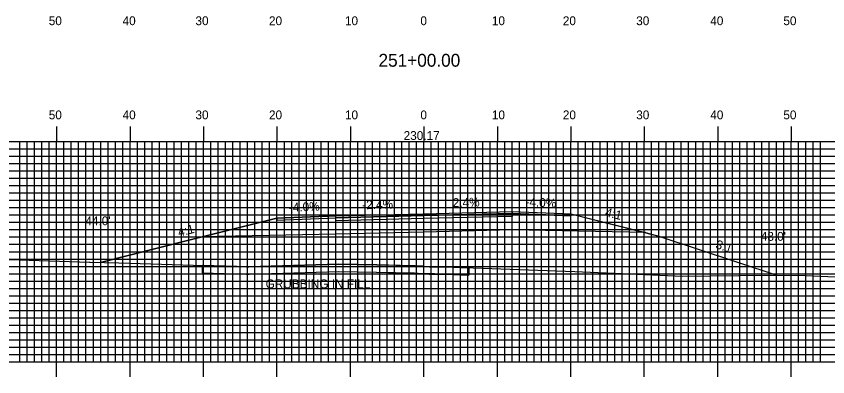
# Model space of a CAD drawing. Extents: x 1803897 to 1804240, y 442591 to 442811.
# Drawn here: x 1804007.2 to 1804117.6, y 442696.7 to 442745.7 of the extents above; entities that cross this region are included whole.
import ezdxf

# ---------------------------------------------------------------- set-up
doc = ezdxf.new("R2010")
doc.units = 0
for name, color, linetype in [('ANNOTATION', 7, 'Continuous'), ('D_Roadway_Centerline', 7, 'Continuous'), ('D_Roadway_Centerline_Text', 7, 'Continuous'), ('D_Roadway_Edge_Shoulder', 7, 'Continuous'), ('D_Roadway_Edge_TW', 7, 'Continuous'), ('D_Roadway_Pavement', 7, 'Continuous'), ('D_Roadway_SlopeLines', 7, 'Continuous'), ('D_Roadway_SubGrade', 7, 'Continuous'), ('D_Text_Standard', 7, 'Continuous'), ('GRUBBING IN FILL', 7, 'Continuous'), ('H_V ANNOTATION', 7, 'Continuous'), ('MAJOR', 7, 'Continuous'), ('MINOR', 7, 'Continuous'), ('S_Roadway_Centerline', 7, 'Continuous')]:
    doc.layers.add(name, color=color, linetype=linetype)

msp = doc.modelspace()

# ---------------------------------------------------------------- linework, layer by layer
at = {"layer": 'D_Roadway_Centerline'}
msp.add_lwpolyline([(1804018.63, 442712.22), (1804030.65, 442715.22), (1804032.48, 442715.68), (1804042.65, 442718.22), (1804050.65, 442718.54), (1804062.65, 442718.83), (1804074.65, 442719.12), (1804082.65, 442718.8), (1804092.83, 442716.26), (1804094.65, 442715.8), (1804110.67, 442710.46)], dxfattribs=at)
at = {"layer": 'D_Roadway_Edge_Shoulder'}
for points in [[(1804074.65, 442719.12), (1804082.65, 442718.8), (1804082.65, 442718.55), (1804074.65, 442718.87)], [(1804050.65, 442718.54), (1804042.65, 442718.22), (1804042.65, 442717.97), (1804050.65, 442718.29)]]:
    msp.add_lwpolyline(points, close=True, dxfattribs=at)
at = {"layer": 'D_Roadway_Edge_TW'}
msp.add_lwpolyline([(1804050.65, 442718.29), (1804050.65, 442718.54), (1804062.65, 442718.83), (1804074.65, 442719.12), (1804074.65, 442718.87), (1804062.65, 442718.58)], close=True, dxfattribs=at)
at = {"layer": 'D_Roadway_Pavement'}
msp.add_lwpolyline([(1804050.65, 442717.88), (1804050.65, 442718.29), (1804062.65, 442718.58), (1804074.65, 442718.87), (1804074.65, 442718.45), (1804062.65, 442718.16)], close=True, dxfattribs=at)
at = {"layer": 'D_Roadway_SlopeLines'}
for points in [[(1804042.65, 442718.22), (1804032.48, 442715.68), (1804030.65, 442715.22), (1804018.63, 442712.22)], [(1804082.65, 442718.8), (1804094.65, 442715.8), (1804110.67, 442710.46)]]:
    msp.add_lwpolyline(points, dxfattribs=at)
at = {"layer": 'D_Roadway_SubGrade'}
msp.add_lwpolyline([(1804050.65, 442716.04), (1804032.48, 442715.68), (1804042.65, 442718.22), (1804042.65, 442717.97), (1804050.65, 442718.29), (1804062.65, 442718.58), (1804074.65, 442718.87), (1804082.65, 442718.55), (1804082.65, 442718.8), (1804092.83, 442716.26), (1804074.65, 442716.62), (1804062.65, 442716.33)], close=True, dxfattribs=at)
at = {"layer": 'GRUBBING IN FILL'}
for p, q in [((1804032.48, 442711.79), (1804032.48, 442710.79)), ((1804032.48, 442711.79), (1804032.48, 442710.79)), ((1804068.75, 442711.48), (1804068.75, 442710.48)), ((1804068.75, 442711.48), (1804068.75, 442710.48)), ((1804065.57, 442710.59), (1804068.75, 442710.48)), ((1804065.57, 442710.59), (1804068.75, 442710.48))]:
    msp.add_line(p, q, dxfattribs=at)
for points in [[(1804032.48, 442711.79), (1804032.48, 442710.79), (1804035.47, 442710.7), (1804038.86, 442710.61), (1804044.94, 442710.79), (1804051.01, 442710.97), (1804056.2, 442710.87), (1804062.65, 442710.68), (1804062.65, 442711.68), (1804056.22, 442711.87), (1804051, 442711.97), (1804044.91, 442711.79), (1804038.82, 442711.61)], [(1804032.48, 442711.79), (1804032.48, 442710.79), (1804035.47, 442710.7), (1804038.86, 442710.61), (1804044.94, 442710.79), (1804051.01, 442710.97), (1804056.2, 442710.87), (1804062.65, 442710.68), (1804062.65, 442711.68), (1804056.22, 442711.87), (1804051, 442711.97), (1804044.91, 442711.79), (1804038.82, 442711.61)], [(1804062.65, 442711.68), (1804065.59, 442711.59), (1804068.75, 442711.48), (1804068.75, 442710.48), (1804065.57, 442710.59), (1804062.65, 442710.68)], [(1804062.65, 442711.68), (1804065.59, 442711.59), (1804068.75, 442711.48), (1804068.75, 442710.48), (1804065.57, 442710.59), (1804062.65, 442710.68)]]:
    msp.add_lwpolyline(points, close=True, dxfattribs=at)
msp.add_lwpolyline([(1804032.48, 442710.79), (1804038.45, 442710.61), (1804038.66, 442710.6), (1804038.86, 442710.61), (1804051.01, 442710.97), (1804061.39, 442710.77), (1804063.35, 442710.63), (1804065.57, 442710.59), (1804065.57, 442710.59)], dxfattribs=at)
msp.add_lwpolyline([(1804032.48, 442710.79), (1804038.45, 442710.61), (1804038.66, 442710.6), (1804038.86, 442710.61), (1804051.01, 442710.97), (1804061.39, 442710.77), (1804063.35, 442710.63), (1804065.57, 442710.59), (1804065.57, 442710.59)], dxfattribs=at)
at = {"layer": 'MAJOR'}
for p, q in [((1804012.65, 442730.67), (1804012.65, 442728.67)), ((1804022.65, 442730.67), (1804022.65, 442728.67)), ((1804032.65, 442730.67), (1804032.65, 442728.67)), ((1804042.65, 442730.67), (1804042.65, 442728.67)), ((1804052.65, 442730.67), (1804052.65, 442728.67)), ((1804062.65, 442730.67), (1804062.65, 442728.67)), ((1804072.65, 442730.67), (1804072.65, 442728.67)), ((1804082.65, 442730.67), (1804082.65, 442728.67)), ((1804092.65, 442730.67), (1804092.65, 442728.67)), ((1804102.65, 442730.67), (1804102.65, 442728.67)), ((1804112.65, 442730.67), (1804112.65, 442728.67)), ((1803922.65, 442728.67), (1804202.65, 442728.67)), ((1803922.65, 442728.67), (1804202.65, 442728.67)), ((1804012.65, 442698.67), (1804012.65, 442728.67)), ((1804022.65, 442698.67), (1804022.65, 442728.67)), ((1804032.65, 442698.67), (1804032.65, 442728.67)), ((1804042.65, 442698.67), (1804042.65, 442728.67)), ((1804052.65, 442698.67), (1804052.65, 442728.67)), ((1804062.65, 442698.67), (1804062.65, 442728.67)), ((1804072.65, 442698.67), (1804072.65, 442728.67)), ((1804082.65, 442698.67), (1804082.65, 442728.67)), ((1804092.65, 442698.67), (1804092.65, 442728.67)), ((1804102.65, 442698.67), (1804102.65, 442728.67)), ((1804112.65, 442698.67), (1804112.65, 442728.67)), ((1803922.65, 442723.67), (1804202.65, 442723.67)), ((1803922.65, 442718.67), (1804202.65, 442718.67)), ((1803922.65, 442713.67), (1804202.65, 442713.67)), ((1803922.65, 442708.67), (1804202.65, 442708.67)), ((1803922.65, 442703.67), (1804202.65, 442703.67)), ((1803922.65, 442698.67), (1804202.65, 442698.67)), ((1803922.65, 442698.67), (1804202.65, 442698.67)), ((1804012.65, 442696.66), (1804012.65, 442698.67)), ((1804022.65, 442696.66), (1804022.65, 442698.67)), ((1804032.65, 442696.66), (1804032.65, 442698.67)), ((1804042.65, 442696.66), (1804042.65, 442698.67)), ((1804052.65, 442696.66), (1804052.65, 442698.67)), ((1804062.65, 442696.66), (1804062.65, 442698.67)), ((1804072.65, 442696.66), (1804072.65, 442698.67)), ((1804082.65, 442696.66), (1804082.65, 442698.67)), ((1804092.65, 442696.66), (1804092.65, 442698.67)), ((1804102.65, 442696.66), (1804102.65, 442698.67)), ((1804112.65, 442696.66), (1804112.65, 442698.67))]:
    msp.add_line(p, q, dxfattribs=at)
at = {"layer": 'MINOR'}
for p, q in [((1803922.65, 442727.67), (1804202.65, 442727.67)), ((1804007.65, 442698.67), (1804007.65, 442728.67)), ((1804008.65, 442698.67), (1804008.65, 442728.67)), ((1804009.65, 442698.67), (1804009.65, 442728.67)), ((1804010.65, 442698.67), (1804010.65, 442728.67)), ((1804011.65, 442698.67), (1804011.65, 442728.67)), ((1804013.65, 442698.67), (1804013.65, 442728.67)), ((1804014.65, 442698.67), (1804014.65, 442728.67)), ((1804015.65, 442698.67), (1804015.65, 442728.67)), ((1804016.65, 442698.67), (1804016.65, 442728.67)), ((1804017.65, 442698.67), (1804017.65, 442728.67)), ((1804018.65, 442698.67), (1804018.65, 442728.67)), ((1804019.65, 442698.67), (1804019.65, 442728.67)), ((1804020.65, 442698.67), (1804020.65, 442728.67)), ((1804021.65, 442698.67), (1804021.65, 442728.67)), ((1804023.65, 442698.67), (1804023.65, 442728.67)), ((1804024.65, 442698.67), (1804024.65, 442728.67)), ((1804025.65, 442698.67), (1804025.65, 442728.67)), ((1804026.65, 442698.67), (1804026.65, 442728.67)), ((1804027.65, 442698.67), (1804027.65, 442728.67)), ((1804028.65, 442698.67), (1804028.65, 442728.67)), ((1804029.65, 442698.67), (1804029.65, 442728.67)), ((1804030.65, 442698.67), (1804030.65, 442728.67)), ((1804031.65, 442698.67), (1804031.65, 442728.67)), ((1804033.65, 442698.67), (1804033.65, 442728.67)), ((1804034.65, 442698.67), (1804034.65, 442728.67)), ((1804035.65, 442698.67), (1804035.65, 442728.67)), ((1804036.65, 442698.67), (1804036.65, 442728.67)), ((1804037.65, 442698.67), (1804037.65, 442728.67)), ((1804038.65, 442698.67), (1804038.65, 442728.67)), ((1804039.65, 442698.67), (1804039.65, 442728.67)), ((1804040.65, 442698.67), (1804040.65, 442728.67)), ((1804041.65, 442698.67), (1804041.65, 442728.67)), ((1804043.65, 442698.67), (1804043.65, 442728.67)), ((1804044.65, 442698.67), (1804044.65, 442728.67)), ((1804045.65, 442698.67), (1804045.65, 442728.67)), ((1804046.65, 442698.67), (1804046.65, 442728.67)), ((1804047.65, 442698.67), (1804047.65, 442728.67)), ((1804048.65, 442698.67), (1804048.65, 442728.67)), ((1804049.65, 442698.67), (1804049.65, 442728.67)), ((1804050.65, 442698.67), (1804050.65, 442728.67)), ((1804051.65, 442698.67), (1804051.65, 442728.67)), ((1804053.65, 442698.67), (1804053.65, 442728.67)), ((1804054.65, 442698.67), (1804054.65, 442728.67)), ((1804055.65, 442698.67), (1804055.65, 442728.67)), ((1804056.65, 442698.67), (1804056.65, 442728.67)), ((1804057.65, 442698.67), (1804057.65, 442728.67)), ((1804058.65, 442698.67), (1804058.65, 442728.67)), ((1804059.65, 442698.67), (1804059.65, 442728.67)), ((1804060.65, 442698.67), (1804060.65, 442728.67)), ((1804061.65, 442698.67), (1804061.65, 442728.67)), ((1804063.65, 442698.67), (1804063.65, 442728.67)), ((1804064.65, 442698.67), (1804064.65, 442728.67)), ((1804065.65, 442698.67), (1804065.65, 442728.67)), ((1804066.65, 442698.67), (1804066.65, 442728.67)), ((1804067.65, 442698.67), (1804067.65, 442728.67)), ((1804068.65, 442698.67), (1804068.65, 442728.67)), ((1804069.65, 442698.67), (1804069.65, 442728.67)), ((1804070.65, 442698.67), (1804070.65, 442728.67)), ((1804071.65, 442698.67), (1804071.65, 442728.67)), ((1804073.65, 442698.67), (1804073.65, 442728.67)), ((1804074.65, 442698.67), (1804074.65, 442728.67)), ((1804075.65, 442698.67), (1804075.65, 442728.67)), ((1804076.65, 442698.67), (1804076.65, 442728.67)), ((1804077.65, 442698.67), (1804077.65, 442728.67)), ((1804078.65, 442698.67), (1804078.65, 442728.67)), ((1804079.65, 442698.67), (1804079.65, 442728.67)), ((1804080.65, 442698.67), (1804080.65, 442728.67)), ((1804081.65, 442698.67), (1804081.65, 442728.67)), ((1804083.65, 442698.67), (1804083.65, 442728.67)), ((1804084.65, 442698.67), (1804084.65, 442728.67)), ((1804085.65, 442698.67), (1804085.65, 442728.67)), ((1804086.65, 442698.67), (1804086.65, 442728.67)), ((1804087.65, 442698.67), (1804087.65, 442728.67)), ((1804088.65, 442698.67), (1804088.65, 442728.67)), ((1804089.65, 442698.67), (1804089.65, 442728.67)), ((1804090.65, 442698.67), (1804090.65, 442728.67)), ((1804091.65, 442698.67), (1804091.65, 442728.67)), ((1804093.65, 442698.67), (1804093.65, 442728.67)), ((1804094.65, 442698.67), (1804094.65, 442728.67)), ((1804095.65, 442698.67), (1804095.65, 442728.67)), ((1804096.65, 442698.67), (1804096.65, 442728.67)), ((1804097.65, 442698.67), (1804097.65, 442728.67)), ((1804098.65, 442698.67), (1804098.65, 442728.67)), ((1804099.65, 442698.67), (1804099.65, 442728.67)), ((1804100.65, 442698.67), (1804100.65, 442728.67)), ((1804101.65, 442698.67), (1804101.65, 442728.67)), ((1804103.65, 442698.67), (1804103.65, 442728.67)), ((1804104.65, 442698.67), (1804104.65, 442728.67)), ((1804105.65, 442698.67), (1804105.65, 442728.67)), ((1804106.65, 442698.67), (1804106.65, 442728.67)), ((1804107.65, 442698.67), (1804107.65, 442728.67)), ((1804108.65, 442698.67), (1804108.65, 442728.67)), ((1804109.65, 442698.67), (1804109.65, 442728.67)), ((1804110.65, 442698.67), (1804110.65, 442728.67)), ((1804111.65, 442698.67), (1804111.65, 442728.67)), ((1804113.65, 442698.67), (1804113.65, 442728.67)), ((1804114.65, 442698.67), (1804114.65, 442728.67)), ((1804115.65, 442698.67), (1804115.65, 442728.67)), ((1804116.65, 442698.67), (1804116.65, 442728.67)), ((1803922.65, 442726.67), (1804202.65, 442726.67)), ((1803922.65, 442725.67), (1804202.65, 442725.67)), ((1803922.65, 442724.67), (1804202.65, 442724.67)), ((1803922.65, 442722.67), (1804202.65, 442722.67)), ((1803922.65, 442721.67), (1804202.65, 442721.67)), ((1803922.65, 442720.67), (1804202.65, 442720.67)), ((1803922.65, 442719.67), (1804202.65, 442719.67)), ((1803922.65, 442717.67), (1804202.65, 442717.67)), ((1803922.65, 442716.67), (1804202.65, 442716.67)), ((1803922.65, 442715.67), (1804202.65, 442715.67)), ((1803922.65, 442714.67), (1804202.65, 442714.67)), ((1803922.65, 442712.67), (1804202.65, 442712.67)), ((1803922.65, 442711.67), (1804202.65, 442711.67)), ((1803922.65, 442710.67), (1804202.65, 442710.67)), ((1803922.65, 442709.67), (1804202.65, 442709.67)), ((1803922.65, 442707.67), (1804202.65, 442707.67)), ((1803922.65, 442706.67), (1804202.65, 442706.67)), ((1803922.65, 442705.67), (1804202.65, 442705.67)), ((1803922.65, 442704.67), (1804202.65, 442704.67)), ((1803922.65, 442702.67), (1804202.65, 442702.67)), ((1803922.65, 442701.67), (1804202.65, 442701.67)), ((1803922.65, 442700.67), (1804202.65, 442700.67)), ((1803922.65, 442699.67), (1804202.65, 442699.67))]:
    msp.add_line(p, q, dxfattribs=at)
at = {"layer": 'S_Roadway_Centerline'}
msp.add_lwpolyline([(1804004.8, 442712.66), (1804017.13, 442712.26), (1804017.17, 442712.26), (1804017.21, 442712.26), (1804021.12, 442712.14), (1804038.49, 442711.61), (1804038.64, 442711.6), (1804038.82, 442711.61), (1804051, 442711.97), (1804061.44, 442711.77), (1804063.39, 442711.63), (1804065.59, 442711.59), (1804083.2, 442710.98), (1804090.63, 442710.67), (1804097.91, 442710.33), (1804105.51, 442710.43), (1804110.2, 442710.46), (1804114.65, 442710.42), (1804127.57, 442709.85)], dxfattribs=at)

# ---------------------------------------------------------------- texts
at = {"layer": 'ANNOTATION'}
for s, rotation, p in [('-4.0%', 2.2906, (1804044.29, 442719.09)), ('-2.4%', 1.3748, (1804054.27, 442719.43)), ('2.4%', 1.3748, (1804066.59, 442719.73)), ('-4.0%', 357.7094, (1804076.45, 442719.85)), ('4:1', 345.9638, (1804087.25, 442718.51)), ('4:1', 14.0362, (1804029.32, 442715.7)), ('3:1', 341.5652, (1804102.27, 442714.17))]:
    msp.add_text(s, height=1.2, rotation=rotation, dxfattribs=at).set_placement(p)
at = {"layer": 'D_Roadway_Centerline'}
for s, p in [('C', (1804062.65, 442718.83)), ('L', (1804062.65, 442718.82))]:
    msp.add_text(s, height=0.0146, dxfattribs=at).set_placement(p)
at = {"layer": 'D_Roadway_Centerline_Text'}
msp.add_text('230.17', height=1.2, dxfattribs=at).set_placement((1804059.89, 442728.86))
at = {"layer": 'D_Text_Standard'}
for s, p in [("44.0'", (1804016.57, 442717.27)), ("48.0'", (1804108.51, 442715.15))]:
    msp.add_text(s, height=1.2, dxfattribs=at).set_placement(p)
at = {"layer": 'GRUBBING IN FILL'}
msp.add_text('GRUBBING IN FILL', height=1.2, rotation=359.9775, dxfattribs=at).set_placement((1804041.1, 442708.7))
at = {"layer": 'H_V ANNOTATION'}
for s, height, p in [('50', 1.2, (1804011.58, 442744.47)), ('40', 1.2, (1804021.63, 442744.47)), ('30', 1.2, (1804031.55, 442744.47)), ('20', 1.2, (1804041.56, 442744.47)), ('10', 1.2, (1804051.9, 442744.47)), ('0', 1.2, (1804062.17, 442744.47)), ('10', 1.2, (1804071.9, 442744.47)), ('20', 1.2, (1804081.56, 442744.47)), ('30', 1.2, (1804091.55, 442744.47)), ('40', 1.2, (1804101.63, 442744.47)), ('50', 1.2, (1804111.58, 442744.47)), ('251+00.00', 1.75, (1804056.47, 442738.82)), ('50', 1.2, (1804011.58, 442731.67)), ('40', 1.2, (1804021.63, 442731.67)), ('30', 1.2, (1804031.55, 442731.67)), ('20', 1.2, (1804041.56, 442731.67)), ('10', 1.2, (1804051.9, 442731.67)), ('0', 1.2, (1804062.17, 442731.67)), ('10', 1.2, (1804071.9, 442731.67)), ('20', 1.2, (1804081.56, 442731.67)), ('30', 1.2, (1804091.55, 442731.67)), ('40', 1.2, (1804101.63, 442731.67)), ('50', 1.2, (1804111.58, 442731.67))]:
    msp.add_text(s, height=height, dxfattribs=at).set_placement(p)

doc.saveas('drawing.dxf')
